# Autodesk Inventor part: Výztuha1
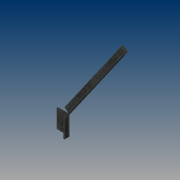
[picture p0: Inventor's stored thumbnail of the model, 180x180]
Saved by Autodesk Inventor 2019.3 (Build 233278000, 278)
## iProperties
Created: 2019-02
Part Number: Výztuha1
Material: Ocel, měkká, svařovaná
Document SubType Name: Plech
Designer: B-hon
Density: 7.85 g/cm^3
Sheet Metal Rule: Výchozí_mm
Appearance: Plech
Author: B-hon
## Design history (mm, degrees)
node "Plocha1"
  sketch "Náčrt1"
    geometry: L1 (-7, 0)-(-48, 0); L2 (-48, 0)-(-48, 390); L3 (-7, 390)-(-7, 0); L4 (-48, 390)-(-7, 390); 5 further points
    constraints: 8 end point, 2 horizontal alignment, 1 horizontal, 1 parallel, 1 perpendicular
    dimensions: "d5" = 7 vertical distance of point (0, 0) point (-17, 7); "d6" = 17 horizontal distance of point (0, 0) point (-17, 7); "d7" = 21 distance of point (-38, 7) point (-17, 7); "d8" = 45 vertical distance of point (-17, 7) point (-27.5, 52); "d9" = 10.5 horizontal distance of point (-17, 7) point (-27.5, 52) (= 0.5 x d7); "d10" = 10 distance from line of point (-17, 7) L3; "d11" = 10 distance from line of point (-38, 7) L2 (= d10); "d12" = 250 distance from line of L3 point (243, 370); "d13" = 370 distance from line of L1 point (243, 370); "d15" = 390 distance of L1.end L2.end
node "Obruba3"
sketch "Náčrt5"
  geometry: L1 (-28.904, 62)-(-14, 62); L2 (-14, 62)-(-14, 60); L3 (-14, 60)-(-28.904, 60); L4 (-28.904, 60)-(-28.904, 62); L5 (-14, 0)-(0, 0) reference; L6 (-14, 390)-(-14, 0) reference; 1 further point
  constraints: 8 end point, 2 parallel, 1 horizontal, 1 perpendicular
  dimensions: "d50" = 60 distance between parallel lines of L5 L3; "d51" = 2 distance of L1.end L2.end; "d52" = 0 distance between parallel lines of L6 L2
extrude "Vysunutí1" cut sketch "Náčrt5" stored distance "d53" = 200; taper "d54" = 0 deg
node "Upravit přímo1"
sketch "Náčrt6"
  geometry: L1 (-9.893, 60)-(57.958, 60); L2 (17, 60)-(20, 60) reference; 1 further point
  constraints: 2 end point, 1 collinear
  dimensions: "d58" = 0 distance between parallel lines of L1 L2
feature "Ohyb součásti1" sketch "Náčrt6" dims "d59" = 3, "d60" = 35 deg
sketch "Náčrt7"
  geometry: L1 (13, 0)-(48, 0) reference; 4 further points
  constraints: 1 horizontal alignment
  dimensions: "d61" = 7 distance from line of L1 point (21, 7); "d62" = 21 horizontal distance of point (0, 0) point (21, 7); "d63" = 21 distance of point (42, 7) point (21, 7); "d64" = 10.5 horizontal distance of point (42, 7) point (31.5, 52) (= 0.5 x d63); "d65" = 45 vertical distance of point (42, 7) point (31.5, 52)
hole "Díra1" sketch "Náčrt7" at (21, 7), (42, 7), (31.5, 52) diameter "d66" = 5.5; stored, may be unused: countersink angle "d70" = 90 deg, drill point angle "d72" = 0 deg; dims "d67" = 6, "d68" = 4, "d69" = 2, "d71" = 3 (= Tloušťka)
node "Upravit přímo2"
node "Těleso1"
feature "Deska1" dims "d14" = 3 (= Tloušťka)
sketch "Náčrt4"
  geometry: L1 through (-195, 0) direction (1, 0); L2 through (0, 10) direction (-3.35e-32, 1); L3 (0, 20)-(-390, 20); L4 (-390, 20)-(-390, 0)
  constraints: 6 end point, 1 horizontal, 1 perpendicular, 1 vertical
feature "Deska4" dims "d14" = 3 (= Tloušťka), "d40" = 3 (= ŠířkaVýštipu), "d41" = 1.5 (= HloubkaVýštipu), "d42" = 6 (= MinimálníZbytek), "d43" = 3 (= PřechodovýPoloměr), "d44" = 20, "d45" = 90 deg, "d46" = 3 (= PoloměrOhybu), "d47" = 12 (= VelikostRohovéhoVýštipu), "d48" = 3 (= VelikostMezery), "d49" = 3 (= VelikostJacobihoPoloměru), "MezeraVystřižení" = 0.01
feature "Ohyb3" dims "d14" = 3 (= Tloušťka), "d40" = 3 (= ŠířkaVýštipu), "d41" = 1.5 (= HloubkaVýštipu), "d42" = 6 (= MinimálníZbytek), "d43" = 3 (= PřechodovýPoloměr), "d44" = 20, "d45" = 90 deg, "d46" = 3 (= PoloměrOhybu), "MezeraVystřižení" = 0.01
feature "Roh3" dims "d44" = 20, "d45" = 90 deg, "d47" = 12 (= VelikostRohovéhoVýštipu), "d48" = 3 (= VelikostMezery), "d49" = 3 (= VelikostJacobihoPoloměru)
feature "Posunout1" dims "d57" = -20
feature "Posunout2" dims "d75" = 1
other parameters: "Tloušťka" = 3 (derived), "KSoučinitel" = 4.4, "PoloměrOhybu" = 3 (= Tloušťka), "ŠířkaVýštipu" = 3 (= Tloušťka), "HloubkaVýštipu" = 1.5 (= 0.5 x Tloušťka), "VelikostRohovéhoVýštipu" = 12 (= 4 x Tloušťka), "MinimálníZbytek" = 6 (= 2 x Tloušťka), "PřechodovýPoloměr" = 3 (= PoloměrOhybu), "VelikostJacobihoPoloměru" = 3 (= PoloměrOhybu), "VelikostMezery" = 3 (= Tloušťka), "d55" = 0, "d56" = 0, "d73" = 0, "d74" = 0
